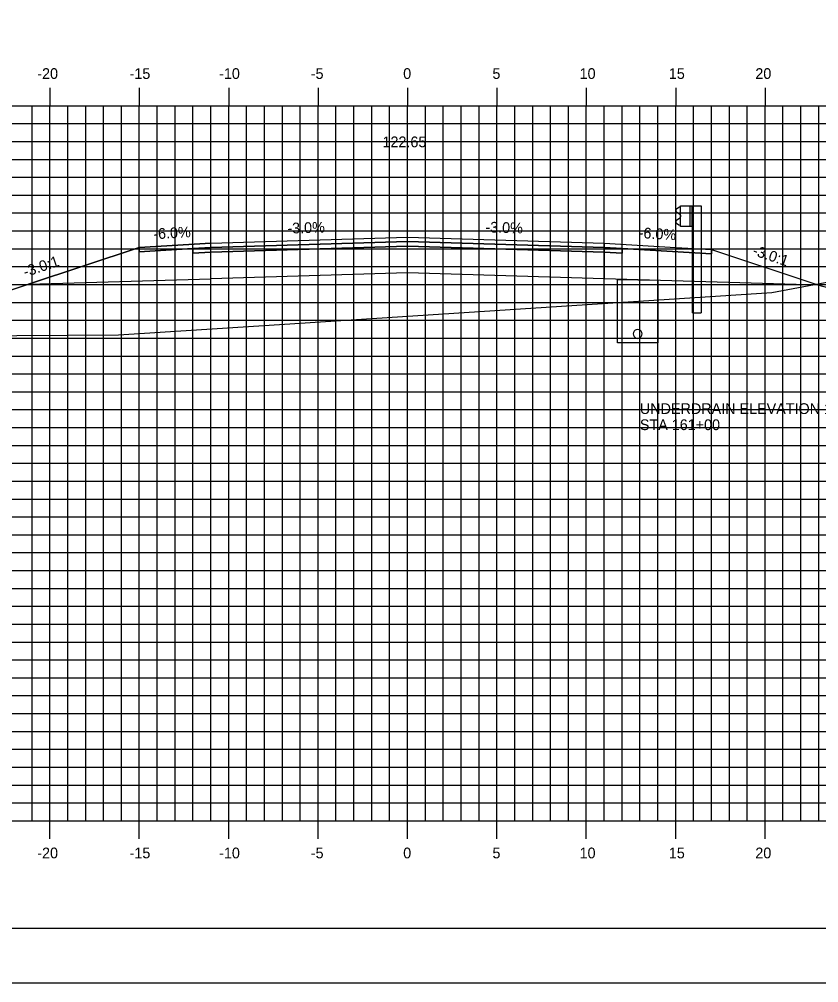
# Model space of a CAD drawing. Extents: x 850598 to 870284, y 366541 to 366651.
# Drawn here: x 853733.8 to 853778.5, y 366541.2 to 366595.1 of the extents above; entities that cross this region are included whole.
import ezdxf

# ---------------------------------------------------------------- set-up
doc = ezdxf.new("R2010")
doc.units = 0
for name, color, linetype in [('ANNOTATION', 7, 'Continuous'), ('BORDER', 7, 'Continuous'), ('D_Drainage_Underdrain', 7, 'Continuous'), ('D_Drainage_Underdrain_06in', 7, 'Continuous'), ('D_Guardrail_Beam_Rt', 7, 'Continuous'), ('D_Roadway_Centerline', 7, 'Continuous'), ('D_Roadway_Centerline_Text', 7, 'Continuous'), ('D_Roadway_Edge_Shoulder', 7, 'Continuous'), ('D_Roadway_Edge_TW', 7, 'Continuous'), ('D_Roadway_Pavement', 7, 'Continuous'), ('D_Roadway_SlopeLines', 7, 'Continuous'), ('D_Roadway_SubGrade', 7, 'Continuous'), ('H_V ANNOTATION', 7, 'Continuous'), ('MAJOR', 7, 'Continuous'), ('MINOR', 7, 'Continuous'), ('PLOT BOUNDARY', 7, 'Continuous'), ('S_Roadway_Centerline', 7, 'Continuous')]:
    doc.layers.add(name, color=color, linetype=linetype)

msp = doc.modelspace()

# ---------------------------------------------------------------- linework, layer by layer
at = {"layer": 'BORDER'}
msp.add_line((853710.489, 366544.225), (853870.489, 366544.225), dxfattribs=at)
at = {"layer": 'D_Drainage_Underdrain'}
msp.add_lwpolyline([(853769.489, 366580.46), (853769.489, 366576.959), (853767.239, 366576.959), (853767.239, 366580.505)], close=True, dxfattribs=at)
at = {"layer": 'D_Drainage_Underdrain_06in'}
msp.add_lwpolyline([(853768.364, 366577.709), (853768.286, 366577.697), (853768.217, 366577.662), (853768.161, 366577.606), (853768.126, 366577.537), (853768.114, 366577.459), (853768.126, 366577.382), (853768.161, 366577.312), (853768.217, 366577.257), (853768.286, 366577.222), (853768.364, 366577.209), (853768.441, 366577.222), (853768.51, 366577.257), (853768.566, 366577.312), (853768.601, 366577.382), (853768.614, 366577.459), (853768.601, 366577.537), (853768.566, 366577.606), (853768.51, 366577.662), (853768.441, 366577.697)], close=True, dxfattribs=at)
at = {"layer": 'D_Guardrail_Beam_Rt'}
for p, q in [((853770.759, 366584.561), (853770.686, 366584.548)), ((853770.759, 366584.635), (853771.447, 366584.635)), ((853770.759, 366583.469), (853770.759, 366584.635)), ((853771.28, 366584.635), (853771.28, 366583.469)), ((853771.384, 366584.635), (853771.384, 366583.469)), ((853771.447, 366584.635), (853771.918, 366584.635)), ((853771.447, 366584.635), (853771.447, 366583.469)), ((853771.918, 366584.635), (853771.918, 366578.635)), ((853770.669, 366584.541), (853770.526, 366584.441)), ((853770.526, 366584.298), (853770.721, 366584.162)), ((853770.755, 366584.097), (853770.755, 366584.006)), ((853770.721, 366583.942), (853770.526, 366583.806)), ((853770.526, 366583.663), (853770.669, 366583.563)), ((853770.686, 366583.556), (853770.759, 366583.543)), ((853771.447, 366583.469), (853770.759, 366583.469)), ((853771.426, 366578.635), (853771.426, 366583.469)), ((853771.426, 366578.635), (853771.918, 366578.635))]:
    msp.add_line(p, q, dxfattribs=at)
for centre, major_axis, start_param, end_param in [((853770.693, 366584.507), (-0.0417, 0), 4.886922, 5.323254), ((853770.576, 366584.369), (-0.0877, 0), 5.323254, 7.243116), ((853770.676, 366584.097), (0.0789, 0), 0, 0.959931), ((853770.676, 366584.006), (0.0789, 0), 5.323254, 6.283185), ((853770.576, 366583.734), (-0.0877, 0), 5.323254, 7.243116), ((853770.693, 366583.597), (-0.0417, 0), 0.959931, 1.396263)]:
    msp.add_ellipse(centre, major_axis=major_axis, ratio=0.995501, start_param=start_param, end_param=end_param, dxfattribs=at)
at = {"layer": 'D_Roadway_Centerline'}
msp.add_lwpolyline([(853725.548, 366577.322), (853730.489, 366578.969), (853734.291, 366580.236), (853740.489, 366582.302), (853744.489, 366582.542), (853755.489, 366582.872), (853766.489, 366582.542), (853770.489, 366582.302), (853772.489, 366582.182), (853778.489, 366580.182), (853822.953, 366568.225), (853835.405, 366564.877), (853845.267, 366562.225), (853849.267, 366562.225)], dxfattribs=at)
at = {"layer": 'D_Roadway_Edge_Shoulder'}
for points in [[(853744.489, 366582.542), (853740.489, 366582.302), (853740.489, 366582.052), (853743.489, 366582.232), (853744.489, 366582.292)], [(853766.489, 366582.542), (853770.489, 366582.302), (853770.489, 366582.302), (853772.489, 366582.182), (853772.489, 366581.932), (853767.489, 366582.232), (853766.489, 366582.292)]]:
    msp.add_lwpolyline(points, close=True, dxfattribs=at)
at = {"layer": 'D_Roadway_Edge_TW'}
msp.add_lwpolyline([(853744.489, 366582.292), (853744.489, 366582.542), (853755.489, 366582.872), (853766.489, 366582.542), (853766.489, 366582.292), (853755.489, 366582.622)], close=True, dxfattribs=at)
at = {"layer": 'D_Roadway_Pavement'}
for points in [[(853744.489, 366582.042), (853744.489, 366582.292), (853755.489, 366582.622), (853766.489, 366582.292), (853766.489, 366582.042), (853755.489, 366582.372)], [(853744.489, 366582.292), (853743.489, 366582.232), (853743.489, 366581.982), (853744.489, 366582.042)], [(853766.489, 366582.292), (853767.489, 366582.232), (853767.489, 366581.982), (853766.489, 366582.042)]]:
    msp.add_lwpolyline(points, close=True, dxfattribs=at)
at = {"layer": 'D_Roadway_SlopeLines'}
msp.add_lwpolyline([(853744.489, 366582.542), (853740.489, 366582.302), (853730.489, 366578.969)], dxfattribs=at)
at = {"layer": 'D_Roadway_SubGrade'}
for points in [[(853744.489, 366582.042), (853743.489, 366581.982), (853743.489, 366582.232), (853740.489, 366582.052), (853740.489, 366582.302), (853734.291, 366580.236), (853744.489, 366580.542)], [(853744.489, 366580.542), (853744.489, 366582.042), (853755.489, 366582.372), (853766.489, 366582.042), (853766.489, 366580.542), (853755.489, 366580.872)], [(853766.489, 366582.042), (853767.489, 366581.982), (853767.489, 366582.232), (853772.489, 366581.932), (853772.489, 366582.182), (853778.489, 366580.182), (853766.489, 366580.542)]]:
    msp.add_lwpolyline(points, close=True, dxfattribs=at)
at = {"layer": 'MAJOR'}
for p, q in [((853735.489, 366591.227), (853735.489, 366590.225)), ((853735.489, 366591.227), (853735.489, 366590.225)), ((853740.489, 366591.227), (853740.489, 366590.225)), ((853740.489, 366591.227), (853740.489, 366590.225)), ((853745.489, 366591.227), (853745.489, 366590.225)), ((853745.489, 366591.227), (853745.489, 366590.225)), ((853750.489, 366591.227), (853750.489, 366590.225)), ((853750.489, 366591.227), (853750.489, 366590.225)), ((853755.489, 366591.227), (853755.489, 366590.225)), ((853755.489, 366591.227), (853755.489, 366590.225)), ((853760.489, 366591.227), (853760.489, 366590.225)), ((853760.489, 366591.227), (853760.489, 366590.225)), ((853765.489, 366591.227), (853765.489, 366590.225)), ((853765.489, 366591.227), (853765.489, 366590.225)), ((853770.489, 366591.227), (853770.489, 366590.225)), ((853770.489, 366591.227), (853770.489, 366590.225)), ((853775.489, 366591.227), (853775.489, 366590.225)), ((853775.489, 366591.227), (853775.489, 366590.225)), ((853715.489, 366590.225), (853855.489, 366590.225)), ((853715.489, 366590.225), (853855.489, 366590.225)), ((853715.489, 366590.225), (853855.489, 366590.225)), ((853715.489, 366590.225), (853855.489, 366590.225)), ((853735.489, 366550.225), (853735.489, 366590.225)), ((853735.489, 366550.225), (853735.489, 366590.225)), ((853740.489, 366550.225), (853740.489, 366590.225)), ((853740.489, 366550.225), (853740.489, 366590.225)), ((853745.489, 366550.225), (853745.489, 366590.225)), ((853745.489, 366550.225), (853745.489, 366590.225)), ((853750.489, 366550.225), (853750.489, 366590.225)), ((853750.489, 366550.225), (853750.489, 366590.225)), ((853755.489, 366550.225), (853755.489, 366590.225)), ((853755.489, 366550.225), (853755.489, 366590.225)), ((853760.489, 366550.225), (853760.489, 366590.225)), ((853760.489, 366550.225), (853760.489, 366590.225)), ((853765.489, 366550.225), (853765.489, 366590.225)), ((853765.489, 366550.225), (853765.489, 366590.225)), ((853770.489, 366550.225), (853770.489, 366590.225)), ((853770.489, 366550.225), (853770.489, 366590.225)), ((853775.489, 366550.225), (853775.489, 366590.225)), ((853775.489, 366550.225), (853775.489, 366590.225)), ((853715.489, 366585.225), (853855.489, 366585.225)), ((853715.489, 366585.225), (853855.489, 366585.225)), ((853715.489, 366580.225), (853855.489, 366580.225)), ((853715.489, 366580.225), (853855.489, 366580.225)), ((853715.489, 366575.225), (853855.489, 366575.225)), ((853715.489, 366575.225), (853855.489, 366575.225)), ((853715.489, 366570.225), (853855.489, 366570.225)), ((853715.489, 366570.225), (853855.489, 366570.225)), ((853715.489, 366565.225), (853855.489, 366565.225)), ((853715.489, 366565.225), (853855.489, 366565.225)), ((853715.489, 366560.225), (853855.489, 366560.225)), ((853715.489, 366560.225), (853855.489, 366560.225)), ((853715.489, 366555.225), (853855.489, 366555.225)), ((853715.489, 366555.225), (853855.489, 366555.225)), ((853715.489, 366550.225), (853855.489, 366550.225)), ((853715.489, 366550.225), (853855.489, 366550.225)), ((853715.489, 366550.225), (853855.489, 366550.225)), ((853715.489, 366550.225), (853855.489, 366550.225)), ((853735.489, 366549.223), (853735.489, 366550.225)), ((853735.489, 366549.223), (853735.489, 366550.225)), ((853740.489, 366549.223), (853740.489, 366550.225)), ((853740.489, 366549.223), (853740.489, 366550.225)), ((853745.489, 366549.223), (853745.489, 366550.225)), ((853745.489, 366549.223), (853745.489, 366550.225)), ((853750.489, 366549.223), (853750.489, 366550.225)), ((853750.489, 366549.223), (853750.489, 366550.225)), ((853755.489, 366549.223), (853755.489, 366550.225)), ((853755.489, 366549.223), (853755.489, 366550.225)), ((853760.489, 366549.223), (853760.489, 366550.225)), ((853760.489, 366549.223), (853760.489, 366550.225)), ((853765.489, 366549.223), (853765.489, 366550.225)), ((853765.489, 366549.223), (853765.489, 366550.225)), ((853770.489, 366549.223), (853770.489, 366550.225)), ((853770.489, 366549.223), (853770.489, 366550.225)), ((853775.489, 366549.223), (853775.489, 366550.225)), ((853775.489, 366549.223), (853775.489, 366550.225))]:
    msp.add_line(p, q, dxfattribs=at)
at = {"layer": 'MINOR'}
for p, q in [((853734.489, 366550.225), (853734.489, 366590.225)), ((853734.489, 366550.225), (853734.489, 366590.225)), ((853736.489, 366550.225), (853736.489, 366590.225)), ((853736.489, 366550.225), (853736.489, 366590.225)), ((853737.489, 366550.225), (853737.489, 366590.225)), ((853737.489, 366550.225), (853737.489, 366590.225)), ((853738.489, 366550.225), (853738.489, 366590.225)), ((853738.489, 366550.225), (853738.489, 366590.225)), ((853739.489, 366550.225), (853739.489, 366590.225)), ((853739.489, 366550.225), (853739.489, 366590.225)), ((853741.489, 366550.225), (853741.489, 366590.225)), ((853741.489, 366550.225), (853741.489, 366590.225)), ((853742.489, 366550.225), (853742.489, 366590.225)), ((853742.489, 366550.225), (853742.489, 366590.225)), ((853743.489, 366550.225), (853743.489, 366590.225)), ((853743.489, 366550.225), (853743.489, 366590.225)), ((853744.489, 366550.225), (853744.489, 366590.225)), ((853744.489, 366550.225), (853744.489, 366590.225)), ((853746.489, 366550.225), (853746.489, 366590.225)), ((853746.489, 366550.225), (853746.489, 366590.225)), ((853747.489, 366550.225), (853747.489, 366590.225)), ((853747.489, 366550.225), (853747.489, 366590.225)), ((853748.489, 366550.225), (853748.489, 366590.225)), ((853748.489, 366550.225), (853748.489, 366590.225)), ((853749.489, 366550.225), (853749.489, 366590.225)), ((853749.489, 366550.225), (853749.489, 366590.225)), ((853751.489, 366550.225), (853751.489, 366590.225)), ((853751.489, 366550.225), (853751.489, 366590.225)), ((853752.489, 366550.225), (853752.489, 366590.225)), ((853752.489, 366550.225), (853752.489, 366590.225)), ((853753.489, 366550.225), (853753.489, 366590.225)), ((853753.489, 366550.225), (853753.489, 366590.225)), ((853754.489, 366550.225), (853754.489, 366590.225)), ((853754.489, 366550.225), (853754.489, 366590.225)), ((853756.489, 366550.225), (853756.489, 366590.225)), ((853756.489, 366550.225), (853756.489, 366590.225)), ((853757.489, 366550.225), (853757.489, 366590.225)), ((853757.489, 366550.225), (853757.489, 366590.225)), ((853758.489, 366550.225), (853758.489, 366590.225)), ((853758.489, 366550.225), (853758.489, 366590.225)), ((853759.489, 366550.225), (853759.489, 366590.225)), ((853759.489, 366550.225), (853759.489, 366590.225)), ((853761.489, 366550.225), (853761.489, 366590.225)), ((853761.489, 366550.225), (853761.489, 366590.225)), ((853762.489, 366550.225), (853762.489, 366590.225)), ((853762.489, 366550.225), (853762.489, 366590.225)), ((853763.489, 366550.225), (853763.489, 366590.225)), ((853763.489, 366550.225), (853763.489, 366590.225)), ((853764.489, 366550.225), (853764.489, 366590.225)), ((853764.489, 366550.225), (853764.489, 366590.225)), ((853766.489, 366550.225), (853766.489, 366590.225)), ((853766.489, 366550.225), (853766.489, 366590.225)), ((853767.489, 366550.225), (853767.489, 366590.225)), ((853767.489, 366550.225), (853767.489, 366590.225)), ((853768.489, 366550.225), (853768.489, 366590.225)), ((853768.489, 366550.225), (853768.489, 366590.225)), ((853769.489, 366550.225), (853769.489, 366590.225)), ((853769.489, 366550.225), (853769.489, 366590.225)), ((853771.489, 366550.225), (853771.489, 366590.225)), ((853771.489, 366550.225), (853771.489, 366590.225)), ((853772.489, 366550.225), (853772.489, 366590.225)), ((853772.489, 366550.225), (853772.489, 366590.225)), ((853773.489, 366550.225), (853773.489, 366590.225)), ((853773.489, 366550.225), (853773.489, 366590.225)), ((853774.489, 366550.225), (853774.489, 366590.225)), ((853774.489, 366550.225), (853774.489, 366590.225)), ((853776.489, 366550.225), (853776.489, 366590.225)), ((853776.489, 366550.225), (853776.489, 366590.225)), ((853777.489, 366550.225), (853777.489, 366590.225)), ((853777.489, 366550.225), (853777.489, 366590.225)), ((853778.489, 366550.225), (853778.489, 366590.225)), ((853778.489, 366550.225), (853778.489, 366590.225)), ((853715.489, 366589.225), (853855.489, 366589.225)), ((853715.489, 366589.225), (853855.489, 366589.225)), ((853715.489, 366588.225), (853855.489, 366588.225)), ((853715.489, 366588.225), (853855.489, 366588.225)), ((853715.489, 366587.225), (853855.489, 366587.225)), ((853715.489, 366587.225), (853855.489, 366587.225)), ((853715.489, 366586.225), (853855.489, 366586.225)), ((853715.489, 366586.225), (853855.489, 366586.225)), ((853715.489, 366584.225), (853855.489, 366584.225)), ((853715.489, 366584.225), (853855.489, 366584.225)), ((853715.489, 366583.225), (853855.489, 366583.225)), ((853715.489, 366583.225), (853855.489, 366583.225)), ((853715.489, 366582.225), (853855.489, 366582.225)), ((853715.489, 366582.225), (853855.489, 366582.225)), ((853715.489, 366581.225), (853855.489, 366581.225)), ((853715.489, 366581.225), (853855.489, 366581.225)), ((853715.489, 366579.225), (853855.489, 366579.225)), ((853715.489, 366579.225), (853855.489, 366579.225)), ((853715.489, 366578.225), (853855.489, 366578.225)), ((853715.489, 366578.225), (853855.489, 366578.225)), ((853715.489, 366577.225), (853855.489, 366577.225)), ((853715.489, 366577.225), (853855.489, 366577.225)), ((853715.489, 366576.225), (853855.489, 366576.225)), ((853715.489, 366576.225), (853855.489, 366576.225)), ((853715.489, 366574.225), (853855.489, 366574.225)), ((853715.489, 366574.225), (853855.489, 366574.225)), ((853715.489, 366573.225), (853855.489, 366573.225)), ((853715.489, 366573.225), (853855.489, 366573.225)), ((853715.489, 366572.225), (853855.489, 366572.225)), ((853715.489, 366572.225), (853855.489, 366572.225)), ((853715.489, 366571.225), (853855.489, 366571.225)), ((853715.489, 366571.225), (853855.489, 366571.225)), ((853715.489, 366569.225), (853855.489, 366569.225)), ((853715.489, 366569.225), (853855.489, 366569.225)), ((853715.489, 366568.225), (853855.489, 366568.225)), ((853715.489, 366568.225), (853855.489, 366568.225)), ((853715.489, 366567.225), (853855.489, 366567.225)), ((853715.489, 366567.225), (853855.489, 366567.225)), ((853715.489, 366566.225), (853855.489, 366566.225)), ((853715.489, 366566.225), (853855.489, 366566.225)), ((853715.489, 366564.225), (853855.489, 366564.225)), ((853715.489, 366564.225), (853855.489, 366564.225)), ((853715.489, 366563.225), (853855.489, 366563.225)), ((853715.489, 366563.225), (853855.489, 366563.225)), ((853715.489, 366562.225), (853855.489, 366562.225)), ((853715.489, 366562.225), (853855.489, 366562.225)), ((853715.489, 366561.225), (853855.489, 366561.225)), ((853715.489, 366561.225), (853855.489, 366561.225)), ((853715.489, 366559.225), (853855.489, 366559.225)), ((853715.489, 366559.225), (853855.489, 366559.225)), ((853715.489, 366558.225), (853855.489, 366558.225)), ((853715.489, 366558.225), (853855.489, 366558.225)), ((853715.489, 366557.225), (853855.489, 366557.225)), ((853715.489, 366557.225), (853855.489, 366557.225)), ((853715.489, 366556.225), (853855.489, 366556.225)), ((853715.489, 366556.225), (853855.489, 366556.225)), ((853715.489, 366554.225), (853855.489, 366554.225)), ((853715.489, 366554.225), (853855.489, 366554.225)), ((853715.489, 366553.225), (853855.489, 366553.225)), ((853715.489, 366553.225), (853855.489, 366553.225)), ((853715.489, 366552.225), (853855.489, 366552.225)), ((853715.489, 366552.225), (853855.489, 366552.225)), ((853715.489, 366551.225), (853855.489, 366551.225)), ((853715.489, 366551.225), (853855.489, 366551.225))]:
    msp.add_line(p, q, dxfattribs=at)
at = {"layer": 'PLOT BOUNDARY'}
msp.add_lwpolyline([(853702.395, 366541.166), (853872.395, 366541.166), (853872.395, 366651.166), (853702.395, 366651.166)], close=True, dxfattribs=at)
at = {"layer": 'S_Roadway_Centerline'}
msp.add_lwpolyline([(853715.489, 366577.258), (853727.93, 366577.337), (853739.322, 366577.409), (853747.757, 366577.946), (853775.869, 366579.776), (853785.205, 366581.53), (853785.911, 366581.674), (853786.364, 366581.76), (853788.576, 366582.055), (853789.791, 366582.106), (853803.328, 366582.644), (853805.352, 366582.582), (853819.384, 366582.138), (853823.386, 366580.873), (853823.494, 366580.831), (853823.71, 366580.659), (853840.663, 366566.181), (853849.375, 366562.176), (853855.489, 366559.284)], dxfattribs=at)

# ---------------------------------------------------------------- texts
at = {"layer": 'ANNOTATION'}
for s, rotation, p in [('-6.0%', 3.4336, (853741.286, 366582.751)), ('-3.0%', 1.7184, (853748.777, 366583.071)), ('-3.0%', 358.2816, (853759.837, 366583.142)), ('-6.0%', 356.5664, (853768.405, 366582.829)), ('-3.0:1', 341.5651, (853774.742, 366581.885)), ('-3.0:1', 18.4348, (853734.11, 366580.63))]:
    msp.add_text(s, height=0.6, rotation=rotation, dxfattribs=at).set_placement(p)
at = {"layer": 'D_Roadway_Centerline'}
for s, p in [('C', (853755.483, 366582.872)), ('C', (853755.483, 366582.872)), ('L', (853755.489, 366582.865)), ('L', (853755.489, 366582.865))]:
    msp.add_text(s, height=0.0146, dxfattribs=at).set_placement(p)
at = {"layer": 'D_Roadway_Centerline_Text'}
msp.add_text('122.65', height=0.6, dxfattribs=at).set_placement((853754.089, 366587.904))
at = {"layer": 'H_V ANNOTATION'}
for s, p in [('-20', (853734.782, 366591.725)), ('-15', (853739.945, 366591.725)), ('-10', (853744.953, 366591.725)), ('-5', (853750.079, 366591.725)), ('0', (853755.248, 366591.725)), ('5', (853760.24, 366591.725)), ('10', (853765.114, 366591.725)), ('15', (853770.106, 366591.725)), ('20', (853774.943, 366591.725)), ('UNDERDRAIN ELEVATION 116.72', (853768.486, 366572.981)), ('STA 161+00', (853768.486, 366572.081)), ('-20', (853734.782, 366548.125)), ('-15', (853739.945, 366548.125)), ('-10', (853744.953, 366548.125)), ('-5', (853750.079, 366548.125)), ('0', (853755.248, 366548.125)), ('5', (853760.24, 366548.125)), ('10', (853765.114, 366548.125)), ('15', (853770.106, 366548.125)), ('20', (853774.943, 366548.125))]:
    msp.add_text(s, height=0.6, dxfattribs=at).set_placement(p)

doc.saveas('drawing.dxf')
